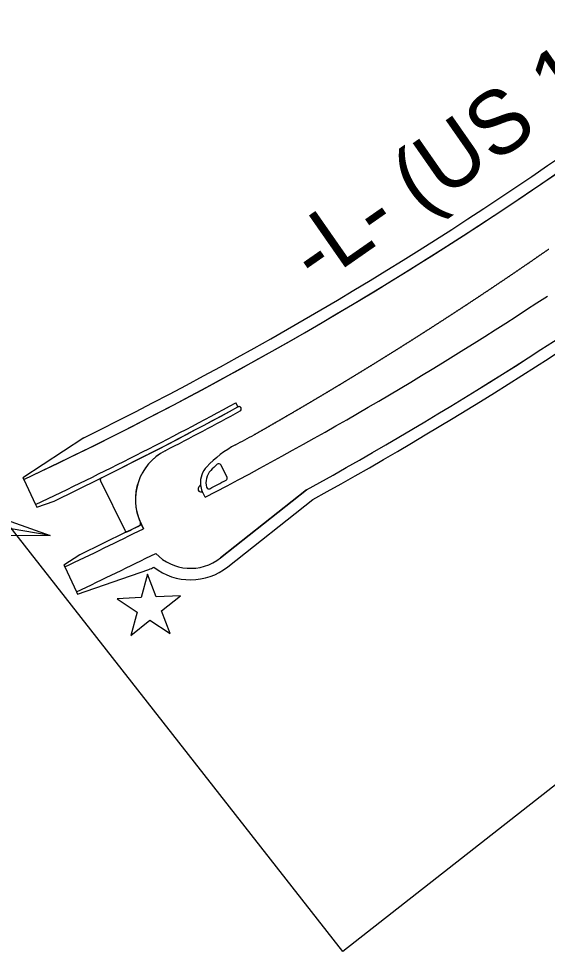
# Model space of a CAD drawing. Extents: x 2170913 to 2188101, y 74009 to 87693.
# Drawn here: x 2175486 to 2175946, y 76229 to 77040 of the extents above; entities that cross this region are included whole.
import ezdxf

# ---------------------------------------------------------------- set-up
doc = ezdxf.new("R2010")
doc.units = 0
for name, color, linetype in [('Exist Hydro Stream or Body of Water', 7, 'Continuous'), ('Exist Property Iron Pin CELL', 7, 'Continuous'), ('Exist Right of Way Monument CELL', 7, 'Continuous'), ('Exist Structure Minor Storm Sewer Manhole CELL', 7, 'Continuous'), ('Exist Utilities Water Fire Hydrant CELL', 7, 'Continuous')]:
    doc.layers.add(name, color=color, linetype=linetype)

msp = doc.modelspace()

# ---------------------------------------------------------------- linework, layer by layer
at = {"layer": 'Exist Hydro Stream or Body of Water'}
msp.add_lwpolyline([(2175592.57, 76536.52), (2175571.54, 76535.52), (2175589.14, 76523.97), (2175583.58, 76503.61), (2175600.04, 76516.81), (2175617.67, 76505.24), (2175610.21, 76524.96), (2175626.65, 76538.14), (2175605.6, 76537.14), (2175598.13, 76556.87), (2175592.57, 76536.52)], dxfattribs=at)
at = {"layer": 'Exist Property Iron Pin CELL'}
msp.add_line((2175513.22, 76590.48), (2174841.11, 76706.17), dxfattribs=at)
at = {"layer": 'Exist Right of Way Monument CELL'}
msp.add_lwpolyline([(2175120.11, 77054.97), (2176300.66, 77980.34), (2176948.42, 77153.96), (2175767.87, 76228.59)], close=True, dxfattribs=at)
at = {"layer": 'Exist Structure Minor Storm Sewer Manhole CELL'}
msp.add_lwpolyline([(2175384.12, 76636.29), (2175513.22, 76590.48), (2175375.36, 76589.85), (2175396.43, 76610.58)], close=True, dxfattribs=at)
at = {"layer": 'Exist Utilities Water Fire Hydrant CELL'}
for p, q in [((2175676.68, 76702.47), (2175674.77, 76705.98)), ((2175674.77, 76705.98), (2175676.68, 76702.47)), ((2175542.53, 76675.65), (2175489.59, 76640.74)), ((2175667.2, 76641.44), (2175661.72, 76651.96)), ((2175489.59, 76640.74), (2175490.25, 76639.35)), ((2175490.25, 76639.35), (2175500.46, 76617.63)), ((2175516.62, 76620.56), (2175556.13, 76639.98)), ((2175557.01, 76638.19), (2175578.22, 76595.12)), ((2175645.64, 76628.72), (2175645.69, 76628.74)), ((2175648.18, 76623.84), (2175646.34, 76627.37)), ((2175736.39, 76630.29), (2175661.59, 76571.07)), ((2175661.59, 76571.07), (2175736.39, 76630.29)), ((2175500.46, 76617.63), (2175501.58, 76615.25)), ((2175501.58, 76615.25), (2175516.62, 76620.56)), ((2175667.8, 76563.23), (2175741.94, 76621.93)), ((2175594.44, 76596.47), (2175592.66, 76600.05)), ((2175592.66, 76600.05), (2175594.44, 76596.47)), ((2175579.1, 76593.33), (2175538.97, 76573.61)), ((2175538.97, 76573.61), (2175525.28, 76564.82)), ((2175525.28, 76564.82), (2175525.98, 76563.33)), ((2175525.98, 76563.33), (2175536.19, 76541.61)), ((2175537.14, 76539.59), (2175599.21, 76560.88)), ((2175536.19, 76541.61), (2175537.14, 76539.59))]:
    msp.add_line(p, q, dxfattribs=at)
msp.add_lwpolyline([(2175645.69, 76628.74), (2175645.64, 76628.72)], dxfattribs=at)
for centre, radius, start, end in [((2174100.8, 79595.05), 3256, 296.28229, 315.12361), ((2174100.8, 79595.05), 3266, 295.17779, 314.67638), ((2174100.8, 79595.05), 3266, 295.17779, 313.3768), ((2174100.8, 79595.05), 3396, 298.89848, 314.1103), ((2174100.8, 79595.05), 3386, 298.88447, 313.18402), ((2174100.8, 79595.05), 3386, 298.88447, 313.18162), ((2174100.8, 79595.05), 3350, 297.51015, 303.42269), ((2174100.8, 79595.05), 3290, 295.17779, 298.5817), ((2174100.8, 79595.05), 3290, 295.17779, 298.5817), ((2174100.8, 79595.05), 3294, 296.21957, 298.5817), ((2174100.8, 79595.05), 3294, 296.25434, 298.5817), ((2174100.8, 79595.05), 3298, 297.30061, 298.5817), ((2174100.8, 79595.05), 3298, 297.30061, 298.5817), ((2175677.64, 76700.72), 2, 298.5817, 118.58194), ((2175677.64, 76700.72), 2, 91.82266, 118.58194), ((2175677.64, 76700.72), 2, 298.5817, 91.82266), ((2174100.8, 79595.05), 3322, 298.27988, 298.59483), ((2175722.07, 76581.49), 100, 118.27988, 136.45359), ((2175635.47, 76621.75), 48, 117.30061, 206.88964), ((2175635.47, 76621.75), 48, 117.30061, 204.58035), ((2175664.08, 76636.6), 20, 136.45359, 184.7173), ((2175722.07, 76581.49), 95.25, 131.77091, 136.45359), ((2175659.95, 76651.04), 2, 27.51015, 131.77091), ((2175558.8, 76639.07), 2, 116.25434, 206.21957), ((2175664.08, 76636.6), 15.25, 136.45359, 195.39236), ((2175665.43, 76640.52), 2, 297.90432, 27.51015), ((2175722.07, 76581.49), 94.5, 145.54033, 147.48912), ((2175722.07, 76581.49), 94.5, 145.54033, 147.48912), ((2175664.08, 76636.6), 20, 184.7173, 203.1525), ((2175651.31, 76633.09), 2, 195.39236, 297.63089), ((2174100.8, 79595.05), 3345.25, 297.63089, 297.90432), ((2175644.48, 76630.93), 2.5, 147.48856, 297.51015), ((2175644.48, 76630.93), 2.5, 147.48856, 297.51015), ((2175664.08, 76636.6), 20, 203.1525, 207.51015), ((2174100.8, 79595.05), 3346, 296.21957, 296.47867), ((2175590, 76600.96), 2, 296.44485, 24.58035), ((2174100.8, 79595.05), 3350, 295.17779, 296.47867), ((2174100.8, 79595.05), 3350, 295.17779, 296.47867), ((2175580.01, 76596.01), 2, 206.21957, 296.25384), ((2174100.8, 79595.05), 3346, 296.25384, 296.44485), ((2174100.8, 79595.05), 3374, 295.17779, 296.47885), ((2174100.8, 79595.05), 3374, 295.17779, 296.47885), ((2175635.52, 76604), 42, 223.69051, 308.36889), ((2175635.52, 76604), 42, 223.69051, 308.36889), ((2174100.8, 79595.05), 3384, 296.28229, 296.36374), ((2175635.52, 76604), 52, 232.02097, 308.36889)]:
    msp.add_arc(centre, radius, start, end, dxfattribs=at)
for points in [[(2175929.46, 76827.6), (2175929.7, 76827.77), (2175930.43, 76828.26), (2175931.15, 76828.76), (2175931.87, 76829.26), (2175932.6, 76829.75), (2175933.32, 76830.25), (2175934.04, 76830.75), (2175934.76, 76831.25), (2175935.49, 76831.75), (2175936.21, 76832.24), (2175936.93, 76832.74), (2175937.65, 76833.24), (2175938.38, 76833.74), (2175939.1, 76834.24), (2175939.82, 76834.74), (2175940.54, 76835.24), (2175941.26, 76835.74), (2175941.98, 76836.24), (2175942.71, 76836.74), (2175943.43, 76837.24), (2175944.15, 76837.74), (2175944.87, 76838.24), (2175945.59, 76838.74), (2175946.31, 76839.24), (2175947.03, 76839.74), (2175947.27, 76839.91)], [(2175911.57, 76815.41), (2175912.3, 76815.9), (2175913.02, 76816.39), (2175913.75, 76816.88), (2175914.48, 76817.38), (2175915.2, 76817.87), (2175915.93, 76818.36), (2175916.66, 76818.85), (2175917.38, 76819.35), (2175918.11, 76819.84), (2175918.83, 76820.34), (2175919.56, 76820.83), (2175920.28, 76821.32), (2175921.01, 76821.82), (2175921.73, 76822.31), (2175922.46, 76822.81), (2175923.18, 76823.3), (2175923.91, 76823.8), (2175924.63, 76824.29), (2175925.36, 76824.79), (2175926.08, 76825.28), (2175926.81, 76825.78), (2175927.53, 76826.28), (2175928.25, 76826.77), (2175928.98, 76827.27), (2175929.46, 76827.6)], [(2175893.59, 76803.33), (2175894.08, 76803.65), (2175894.81, 76804.14), (2175895.54, 76804.63), (2175896.27, 76805.12), (2175897, 76805.6), (2175897.73, 76806.09), (2175898.46, 76806.58), (2175899.19, 76807.07), (2175899.92, 76807.56), (2175900.65, 76808.05), (2175901.38, 76808.54), (2175902.11, 76809.03), (2175902.84, 76809.52), (2175903.56, 76810.01), (2175904.29, 76810.5), (2175905.02, 76810.99), (2175905.75, 76811.48), (2175906.48, 76811.97), (2175907.21, 76812.46), (2175907.93, 76812.95), (2175908.66, 76813.44), (2175909.39, 76813.93), (2175910.12, 76814.42), (2175910.84, 76814.91), (2175911.57, 76815.41)], [(2175875.54, 76791.36), (2175875.79, 76791.53), (2175876.52, 76792.01), (2175877.25, 76792.49), (2175877.99, 76792.97), (2175878.72, 76793.46), (2175879.45, 76793.94), (2175880.19, 76794.43), (2175880.92, 76794.91), (2175881.65, 76795.39), (2175882.38, 76795.88), (2175883.12, 76796.36), (2175883.85, 76796.85), (2175884.58, 76797.33), (2175885.31, 76797.82), (2175886.04, 76798.3), (2175886.78, 76798.79), (2175887.51, 76799.27), (2175888.24, 76799.76), (2175888.97, 76800.24), (2175889.7, 76800.73), (2175890.43, 76801.22), (2175891.16, 76801.7), (2175891.89, 76802.19), (2175892.62, 76802.68), (2175893.35, 76803.16), (2175893.59, 76803.33)], [(2175857.41, 76779.52), (2175858.15, 76780), (2175858.88, 76780.48), (2175859.62, 76780.95), (2175860.36, 76781.43), (2175861.09, 76781.91), (2175861.83, 76782.39), (2175862.56, 76782.87), (2175863.3, 76783.35), (2175864.04, 76783.83), (2175864.77, 76784.31), (2175865.51, 76784.79), (2175866.24, 76785.27), (2175866.98, 76785.75), (2175867.71, 76786.23), (2175868.45, 76786.71), (2175869.18, 76787.19), (2175869.92, 76787.67), (2175870.65, 76788.15), (2175871.38, 76788.63), (2175872.12, 76789.11), (2175872.85, 76789.6), (2175873.59, 76790.08), (2175874.32, 76790.56), (2175875.05, 76791.04), (2175875.54, 76791.36)], [(2175839.2, 76767.79), (2175839.69, 76768.11), (2175840.43, 76768.58), (2175841.17, 76769.05), (2175841.91, 76769.53), (2175842.65, 76770), (2175843.39, 76770.48), (2175844.13, 76770.95), (2175844.87, 76771.42), (2175845.61, 76771.9), (2175846.34, 76772.37), (2175847.08, 76772.85), (2175847.82, 76773.32), (2175848.56, 76773.8), (2175849.3, 76774.27), (2175850.04, 76774.75), (2175850.77, 76775.23), (2175851.51, 76775.7), (2175852.25, 76776.18), (2175852.99, 76776.66), (2175853.72, 76777.13), (2175854.46, 76777.61), (2175855.2, 76778.09), (2175855.94, 76778.56), (2175856.67, 76779.04), (2175857.41, 76779.52)], [(2175820.91, 76756.18), (2175821.16, 76756.34), (2175821.9, 76756.81), (2175822.64, 76757.27), (2175823.38, 76757.74), (2175824.13, 76758.21), (2175824.87, 76758.68), (2175825.61, 76759.15), (2175826.35, 76759.62), (2175827.1, 76760.09), (2175827.84, 76760.56), (2175828.58, 76761.03), (2175829.32, 76761.5), (2175830.06, 76761.97), (2175830.8, 76762.44), (2175831.55, 76762.91), (2175832.29, 76763.38), (2175833.03, 76763.86), (2175833.77, 76764.33), (2175834.51, 76764.8), (2175835.25, 76765.27), (2175835.99, 76765.74), (2175836.73, 76766.22), (2175837.47, 76766.69), (2175838.21, 76767.16), (2175838.95, 76767.63), (2175839.2, 76767.79)], [(2175802.54, 76744.69), (2175803.29, 76745.15), (2175804.03, 76745.62), (2175804.78, 76746.08), (2175805.52, 76746.54), (2175806.27, 76747.01), (2175807.01, 76747.47), (2175807.76, 76747.94), (2175808.51, 76748.4), (2175809.25, 76748.87), (2175810, 76749.33), (2175810.74, 76749.8), (2175811.48, 76750.26), (2175812.23, 76750.73), (2175812.97, 76751.2), (2175813.72, 76751.66), (2175814.46, 76752.13), (2175815.21, 76752.6), (2175815.95, 76753.06), (2175816.69, 76753.53), (2175817.44, 76754), (2175818.18, 76754.46), (2175818.93, 76754.93), (2175819.67, 76755.4), (2175820.41, 76755.87), (2175820.91, 76756.18)], [(2175784.09, 76733.31), (2175784.59, 76733.62), (2175785.34, 76734.08), (2175786.09, 76734.54), (2175786.84, 76735), (2175787.59, 76735.46), (2175788.34, 76735.92), (2175789.09, 76736.38), (2175789.84, 76736.84), (2175790.58, 76737.3), (2175791.33, 76737.76), (2175792.08, 76738.22), (2175792.83, 76738.68), (2175793.58, 76739.14), (2175794.32, 76739.6), (2175795.07, 76740.06), (2175795.82, 76740.52), (2175796.57, 76740.99), (2175797.31, 76741.45), (2175798.06, 76741.91), (2175798.81, 76742.37), (2175799.55, 76742.84), (2175800.3, 76743.3), (2175801.05, 76743.76), (2175801.79, 76744.22), (2175802.54, 76744.69)], [(2175765.57, 76722.06), (2175765.82, 76722.21), (2175766.58, 76722.67), (2175767.33, 76723.12), (2175768.08, 76723.57), (2175768.83, 76724.03), (2175769.58, 76724.48), (2175770.34, 76724.94), (2175771.09, 76725.39), (2175771.84, 76725.85), (2175772.59, 76726.31), (2175773.34, 76726.76), (2175774.09, 76727.22), (2175774.84, 76727.67), (2175775.59, 76728.13), (2175776.35, 76728.59), (2175777.1, 76729.04), (2175777.85, 76729.5), (2175778.6, 76729.96), (2175779.35, 76730.41), (2175780.1, 76730.87), (2175780.85, 76731.33), (2175781.6, 76731.79), (2175782.35, 76732.25), (2175783.1, 76732.7), (2175783.85, 76733.16), (2175784.09, 76733.31)], [(2175746.98, 76710.93), (2175747.73, 76711.38), (2175748.49, 76711.83), (2175749.24, 76712.27), (2175750, 76712.72), (2175750.75, 76713.17), (2175751.51, 76713.62), (2175752.26, 76714.07), (2175753.02, 76714.52), (2175753.77, 76714.98), (2175754.53, 76715.43), (2175755.28, 76715.88), (2175756.03, 76716.33), (2175756.79, 76716.78), (2175757.54, 76717.23), (2175758.3, 76717.68), (2175759.05, 76718.14), (2175759.8, 76718.59), (2175760.56, 76719.04), (2175761.31, 76719.49), (2175762.06, 76719.95), (2175762.81, 76720.4), (2175763.57, 76720.85), (2175764.32, 76721.3), (2175765.07, 76721.76), (2175765.57, 76722.06)], [(2175728.31, 76699.91), (2175728.81, 76700.21), (2175729.57, 76700.65), (2175730.33, 76701.1), (2175731.09, 76701.54), (2175731.85, 76701.99), (2175732.6, 76702.43), (2175733.36, 76702.88), (2175734.12, 76703.32), (2175734.88, 76703.77), (2175735.63, 76704.22), (2175736.39, 76704.66), (2175737.15, 76705.11), (2175737.9, 76705.55), (2175738.66, 76706), (2175739.42, 76706.45), (2175740.17, 76706.89), (2175740.93, 76707.34), (2175741.69, 76707.79), (2175742.44, 76708.24), (2175743.2, 76708.68), (2175743.96, 76709.13), (2175744.71, 76709.58), (2175745.47, 76710.03), (2175746.22, 76710.48), (2175746.98, 76710.93)], [(2175709.56, 76689.02), (2175709.82, 76689.17), (2175710.58, 76689.61), (2175711.34, 76690.05), (2175712.1, 76690.49), (2175712.86, 76690.93), (2175713.62, 76691.37), (2175714.38, 76691.81), (2175715.14, 76692.25), (2175715.9, 76692.69), (2175716.66, 76693.13), (2175717.42, 76693.57), (2175718.19, 76694.01), (2175718.94, 76694.45), (2175719.7, 76694.89), (2175720.46, 76695.34), (2175721.22, 76695.78), (2175721.98, 76696.22), (2175722.74, 76696.66), (2175723.5, 76697.1), (2175724.26, 76697.55), (2175725.02, 76697.99), (2175725.78, 76698.43), (2175726.54, 76698.88), (2175727.3, 76699.32), (2175728.06, 76699.77), (2175728.31, 76699.91)], [(2175690.75, 76678.25), (2175691.51, 76678.68), (2175692.28, 76679.12), (2175693.04, 76679.55), (2175693.8, 76679.99), (2175694.57, 76680.42), (2175695.33, 76680.86), (2175696.09, 76681.29), (2175696.86, 76681.73), (2175697.62, 76682.16), (2175698.38, 76682.6), (2175699.15, 76683.04), (2175699.91, 76683.47), (2175700.67, 76683.91), (2175701.44, 76684.35), (2175702.2, 76684.78), (2175702.96, 76685.22), (2175703.72, 76685.66), (2175704.49, 76686.1), (2175705.25, 76686.54), (2175706.01, 76686.97), (2175706.77, 76687.41), (2175707.53, 76687.85), (2175708.29, 76688.29), (2175709.06, 76688.73), (2175709.56, 76689.02)]]:
    msp.add_spline(points, degree=3, dxfattribs=at)

# ---------------------------------------------------------------- texts
at = {"layer": 'Exist Property Iron Pin CELL'}
msp.add_text('-L- (US 17)', height=55.0465, rotation=34.86558, dxfattribs=at).set_placement((2175744.94, 76806.49))

doc.saveas('drawing.dxf')
